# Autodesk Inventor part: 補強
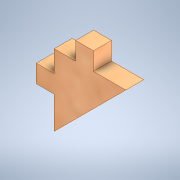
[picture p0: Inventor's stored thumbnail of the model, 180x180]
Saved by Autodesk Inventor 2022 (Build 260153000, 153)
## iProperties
Created: 2024-12
Part Number: 補強
Material: MDF 中密度繊維ボード
Document SubType Name: Modeling
Designer: shimizu
Density: 0.8 g/cm^3
Appearance: サクラ材 - ナチュラル 抑えた光沢
Author: shimizu
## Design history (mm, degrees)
sketch "スケッチ2"
  geometry: L1 (-5.085, 3.641)-(4.915, 3.641); L2 (4.915, 3.641)-(4.915, -6.359); L3 (4.915, -6.359)-(-5.085, -6.359); L4 (-5.085, -6.359)-(-5.085, 3.641); L5 (4.915, 3.641)-(-5.085, -6.359); L6 (-2.085, 3.641)-(0.415, 3.641); L7 (0.415, 3.641)-(0.415, 6.141); L8 (0.415, 6.141)-(-2.085, 6.141); L9 (-2.085, 6.141)-(-2.085, 3.641); L10 (-5.085, 0.641)-(-7.585, 0.641); L11 (-7.585, 0.641)-(-7.585, -1.859); L12 (-7.585, -1.859)-(-5.085, -1.859); L13 (-5.085, -1.859)-(-5.085, 0.641); 3 further points
  constraints: 26 end point, 6 parallel, 3 horizontal, 3 perpendicular, 2 point on line
  dimensions: "d13" = 10 distance of L1.start L1.end; "d14" = 10 distance of L3.end L1.start; "d15" = 2.5 distance of L7.end L8.end; "d16" = 2.5 distance of L6.end L7.end; "d17" = 2.5 distance of L10.start L10.end; "d18" = 2.5 distance of L10.end L11.end; "d19" = 3 distance between parallel lines of L9 L4; "d20" = 3 distance between parallel lines of L10 L1
extrude "押し出し2" new body sketch "スケッチ2" distance "d21" = 2.5; taper "d22" = 0 deg
node "ソリッド2"
other parameters: "d0" = 8
